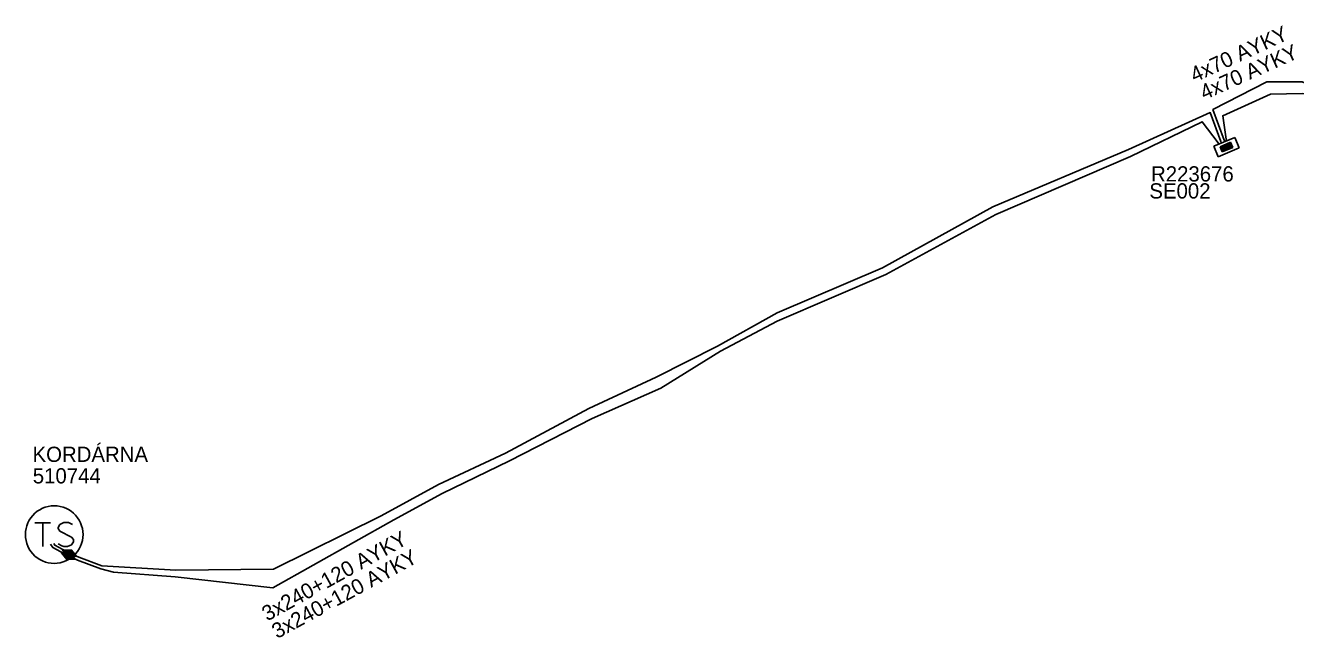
# Model space of a CAD drawing. Extents: x -536149 to -535465, y -1201639 to -1201298.
# Drawn here: x -535808.5 to -535725.2, y -1201338.6 to -1201298.4 of the extents above; entities that cross this region are included whole.
import ezdxf

# ---------------------------------------------------------------- set-up
doc = ezdxf.new("R2010")
doc.units = 0
for name, color, linetype in [('Vrstva 19', 7, 'Continuous'), ('Vrstva 25', 7, 'Continuous'), ('Vrstva 26', 7, 'Continuous'), ('Vrstva 27', 7, 'Continuous'), ('Vrstva 28', 7, 'Continuous'), ('Vrstva 29', 7, 'Continuous'), ('Vrstva 30', 7, 'Continuous'), ('Vrstva 4', 7, 'Continuous'), ('Vrstva 5', 7, 'Continuous'), ('Vrstva 6', 7, 'Continuous'), ('Vrstva 8', 7, 'Continuous')]:
    doc.layers.add(name, color=color, linetype=linetype)

# ---------------------------------------------------------------- blocks, each defined once
blk = doc.blocks.new('NN870')
at = {"layer": 'Vrstva 4'}
for points in [[(0, -0.251), (0.5, 0.001), (0, 0.249), (-0.5, 0.001), (0, -0.251)], [(0.37, -0.003), (0, 0.186), (-0.362, 0.001), (0, -0.188), (0.37, -0.003)], [(0.245, -0.003), (0, 0.123), (-0.252, -0.003), (0, -0.125), (0.245, -0.003)], [(0.122, -0.003), (0, 0.06), (-0.13, -0.003), (0, -0.062), (0.122, -0.003)]]:
    blk.add_lwpolyline(points, dxfattribs=at)
blk = doc.blocks.new('NN620')
at = {"layer": 'Vrstva 8'}
for points in [[(0.752, 0.004), (-0.748, 0.004)], [(-0.748, 0.004), (-0.748, -0.746)], [(0.752, -0.746), (0.752, 0.004)], [(-0.748, -0.746), (0.752, -0.746)], [(0.368, -0.18), (-0.376, -0.18)], [(-0.376, -0.18), (-0.376, -0.558)], [(-0.376, -0.558), (0.368, -0.558)], [(0.321, -0.227), (-0.329, -0.227)], [(-0.329, -0.227), (-0.329, -0.51)], [(-0.329, -0.51), (0.321, -0.51)], [(0.274, -0.274), (-0.281, -0.274)], [(-0.281, -0.274), (-0.281, -0.463)], [(-0.281, -0.463), (0.274, -0.463)], [(0.227, -0.321), (-0.234, -0.321)], [(-0.234, -0.321), (-0.234, -0.416)], [(-0.234, -0.416), (0.227, -0.416)], [(-0.193, -0.369), (0.185, -0.369)], [(0.227, -0.416), (0.227, -0.321)], [(0.274, -0.463), (0.274, -0.274)], [(0.321, -0.51), (0.321, -0.227)], [(0.368, -0.558), (0.368, -0.18)]]:
    blk.add_lwpolyline(points, dxfattribs=at)
blk = doc.blocks.new('NN610')
at = {"layer": 'Vrstva 6'}
for points in [[(1.883, -0.001), (1.872, 0.196), (1.841, 0.392), (1.79, 0.583), (1.718, 0.768), (1.629, 0.943), (1.521, 1.109), (1.397, 1.263), (1.257, 1.403), (1.103, 1.527), (0.937, 1.635), (0.761, 1.725), (0.577, 1.796), (0.19, 1.878), (0.19, 1.878), (-0.007, 1.889), (-0.205, 1.878), (-0.401, 1.847), (-0.591, 1.796), (-0.777, 1.725), (-0.952, 1.635), (-1.118, 1.527), (-1.272, 1.403), (-1.412, 1.263), (-1.536, 1.109), (-1.644, 0.943), (-1.734, 0.768), (-1.805, 0.583), (-1.856, 0.392), (-1.887, 0.196), (-1.898, -0.001), (-1.887, -0.199), (-1.856, -0.395), (-1.805, -0.585), (-1.734, -0.77), (-1.644, -0.946), (-1.536, -1.112), (-1.411, -1.266), (-1.272, -1.405), (-1.118, -1.53), (-0.952, -1.638), (-0.776, -1.728), (-0.591, -1.799), (-0.401, -1.85), (-0.205, -1.881), (-0.007, -1.892), (0.19, -1.881), (0.385, -1.85), (0.577, -1.799), (0.761, -1.728), (0.937, -1.638), (1.103, -1.53), (1.257, -1.405), (1.397, -1.266), (1.521, -1.112), (1.629, -0.946), (1.718, -0.77), (1.79, -0.585), (1.841, -0.395), (1.872, -0.199), (1.883, -0.001)], [(-1.269, 0.782), (-0.261, 0.782)], [(-0.765, 0.782), (-0.765, -0.792)], [(1.188, 0.656), (0.936, 0.782), (0.621, 0.782), (0.369, 0.656), (0.243, 0.468), (0.243, 0.404), (0.369, 0.216), (1.125, -0.162), (1.251, -0.32), (1.251, -0.478), (1.125, -0.666), (0.873, -0.792), (0.621, -0.792), (0.495, -0.73), (0.243, -0.604)]]:
    blk.add_lwpolyline(points, dxfattribs=at)

msp = doc.modelspace()

# ---------------------------------------------------------------- linework, layer by layer
at = {"layer": 'Vrstva 5'}
for points in [[(-535722.56, -1201303.26), (-535722.98, -1201302.84), (-535724.72, -1201302.08), (-535727.05, -1201302.08), (-535730.58, -1201303.91), (-535729.84, -1201305.91), (-535729.806, -1201305.993)], [(-535721.944, -1201304.366), (-535723.15, -1201302.96), (-535724.7, -1201302.86), (-535726.8, -1201302.91), (-535729.94, -1201304.32), (-535729.71, -1201305.86), (-535729.675, -1201305.938)], [(-535805.704, -1201333.2), (-535805.098, -1201333.473), (-535803.575, -1201334.044), (-535802.73, -1201334.26), (-535798.69, -1201334.57), (-535792.28, -1201335.29), (-535784.34, -1201330.83), (-535781.16, -1201329.1), (-535776.75, -1201326.95), (-535771.32, -1201324.19), (-535766.82, -1201322.2), (-535762.9, -1201319.76), (-535759.18, -1201317.8), (-535752.05, -1201314.74), (-535744.82, -1201310.8), (-535735.99, -1201306.98), (-535731.28, -1201304.71), (-535730.24, -1201306.09), (-535730.209, -1201306.162)], [(-535730.036, -1201306.089), (-535730.07, -1201306.01), (-535730.76, -1201304.11), (-535736.13, -1201306.52), (-535745.03, -1201310.3), (-535752.27, -1201314.3), (-535759.19, -1201317.24), (-535763.1, -1201319.44), (-535767.12, -1201321.48), (-535771.55, -1201323.53), (-535777.02, -1201326.45), (-535781.41, -1201328.52), (-535785.17, -1201330.56), (-535792.23, -1201334.07), (-535798.65, -1201334.13), (-535803.505, -1201333.856), (-535805.022, -1201333.287), (-535805.617, -1201333.02)], [(-535806.878, -1201332.419), (-535806.719, -1201332.656), (-535805.704, -1201333.2)], [(-535805.617, -1201333.02), (-535806.581, -1201332.504), (-535806.662, -1201332.381)]]:
    msp.add_lwpolyline(points, dxfattribs=at)

# ---------------------------------------------------------------- block references
at = {"layer": 'Vrstva 19'}
for p, rotation in [((-535805.704, -1201333.2), -25.056836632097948), ((-535805.617, -1201333.02), -22.786320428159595)]:
    msp.add_blockref('NN870', p, dxfattribs=dict(at, rotation=rotation))
at = {"layer": 'Vrstva 25', "rotation": 0.028511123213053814}
msp.add_blockref('NN610', (-535806.62, -1201331.8), dxfattribs=at)
at = {"layer": 'Vrstva 28', "rotation": 22.70682228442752}
msp.add_blockref('NN620', (-535729.838, -1201306.034), dxfattribs=at)

# ---------------------------------------------------------------- texts
at = {"layer": 'Vrstva 26'}
msp.add_text('510744', height=1, rotation=0.029, dxfattribs=at).set_placement((-535808.035, -1201328.444))
at = {"layer": 'Vrstva 27'}
msp.add_text('KORDÁRNA', height=1, rotation=0.029, dxfattribs=at).set_placement((-535808.05, -1201327.033))
at = {"layer": 'Vrstva 29'}
msp.add_text('R223676', height=1, dxfattribs=at).set_placement((-535734.643, -1201308.63))
at = {"layer": 'Vrstva 30'}
msp.add_text('SE002', height=1, dxfattribs=at).set_placement((-535734.754, -1201309.747))
at = {"layer": 'Vrstva 6'}
for s, rotation, p in [('4x70 AYKY', 24.726, (-535731.779, -1201302.144)), ('4x70 AYKY', 24.182, (-535731.145, -1201303.299)), ('3x240+120 AYKY', 28.92, (-535792.646, -1201337.513)), ('3x240+120 AYKY', 28.588, (-535792, -1201338.659))]:
    msp.add_text(s, height=1, rotation=rotation, dxfattribs=at).set_placement(p)

doc.saveas('drawing.dxf')
